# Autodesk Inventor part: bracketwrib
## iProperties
Author: Administrator
Created: 2001-01
Part Number: bracketwrib
Document SubType Name: Modeling
Designer: Administrator
Control State: 0
Master: False
Checked Out: False
PropertySet Name: Design Tracking Control
Shininess: 0.0
PropertySet Name: _Private Model Information
Density: 0.0
Volumn: 0.0
Area: 0.0
PropertySet Name: Model Information
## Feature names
1. Extrusion1
2. Extrusion2
3. Hole1
4. Fillet1
5. Extrusion3
6. Hole2
7. Rectangular Pattern1
8. Fillet2
9. Fillet3
10. Fillet4
11. Fillet5
